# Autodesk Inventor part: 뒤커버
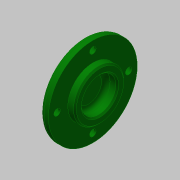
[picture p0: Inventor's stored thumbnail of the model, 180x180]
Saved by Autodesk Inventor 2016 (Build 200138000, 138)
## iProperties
Created: 2015-12
Part Number: 뒤커버
Document SubType Name: Modeling
Designer: mdu
Density: 2.71 g/cm^3
Material: 알루미늄 6061
Appearance: 진녹색
Mass: 56.2003 g
Surface Area: 84.0408 cm^2
Volume: 20.7381 cm^3
Author: mdu
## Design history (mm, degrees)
sketch "스케치1"
  geometry: L1 (-7, 0)-(7, 0); L2 (-7, 0)-(-7, 15.539); L3 (-7, 15.539)-(-4, 18.5); L4 (-4, 18.5)-(-4, 31); L5 (-4, 31)-(2, 31); L6 (2, 31)-(2, 17.5); L7 (2, 17.5)-(7, 17.5); L8 (7, 17.5)-(7, 0); 2 further points
  constraints: 16 end point, 4 parallel, 2 perpendicular, 1 coincident, 1 horizontal, 1 midpoint
  dimensions: "d0" = 14 distance of L1.start L1.end; "d1" = 62 diameter of L5 L1; "d2" = 35 diameter of L7 L1; "d3" = 37 diameter of L3.end L1; "d4" = 3 distance between parallel lines of L4 L2; "d5" = 6 distance of L4.end L5.end
revolve "회전1" sketch "스케치1" stored, may be unused: angle "d6" = 90 deg
sketch "스케치2" dims "d32" = 50
  geometry: 3 further points
  constraints: 2 vertical alignment, 1 coincident, 2 other
hole "구멍1" sketch "스케치2" at (0, 25) diameter "d8" = 4.5; stored, may be unused: countersink angle "d12" = 90 deg, drill point angle "d14" = 118 deg; dims "d9" = 6, "d10" = 8, "d11" = 4.4, "d13" = 8
hole "구멍2" diameter "d20" = 24; stored, may be unused: countersink angle "d24" = 90 deg, drill point angle "d26" = 0 deg; dims "d18" = 10, "d19" = 10, "d21" = 6, "d22" = 8, "d23" = 4.4, "d25" = 8
fillet "모깎기1" dims "d27" = 3
fillet "모깎기2" dims "d28" = 3
chamfer "모따기1" distance "d29" = 1; stored, may be unused: second distance "d30" = 2, angle "d31" = 45 deg
node "솔리드1"
pattern_circular "원형 패턴1" dims angle "d16" = 360 deg
